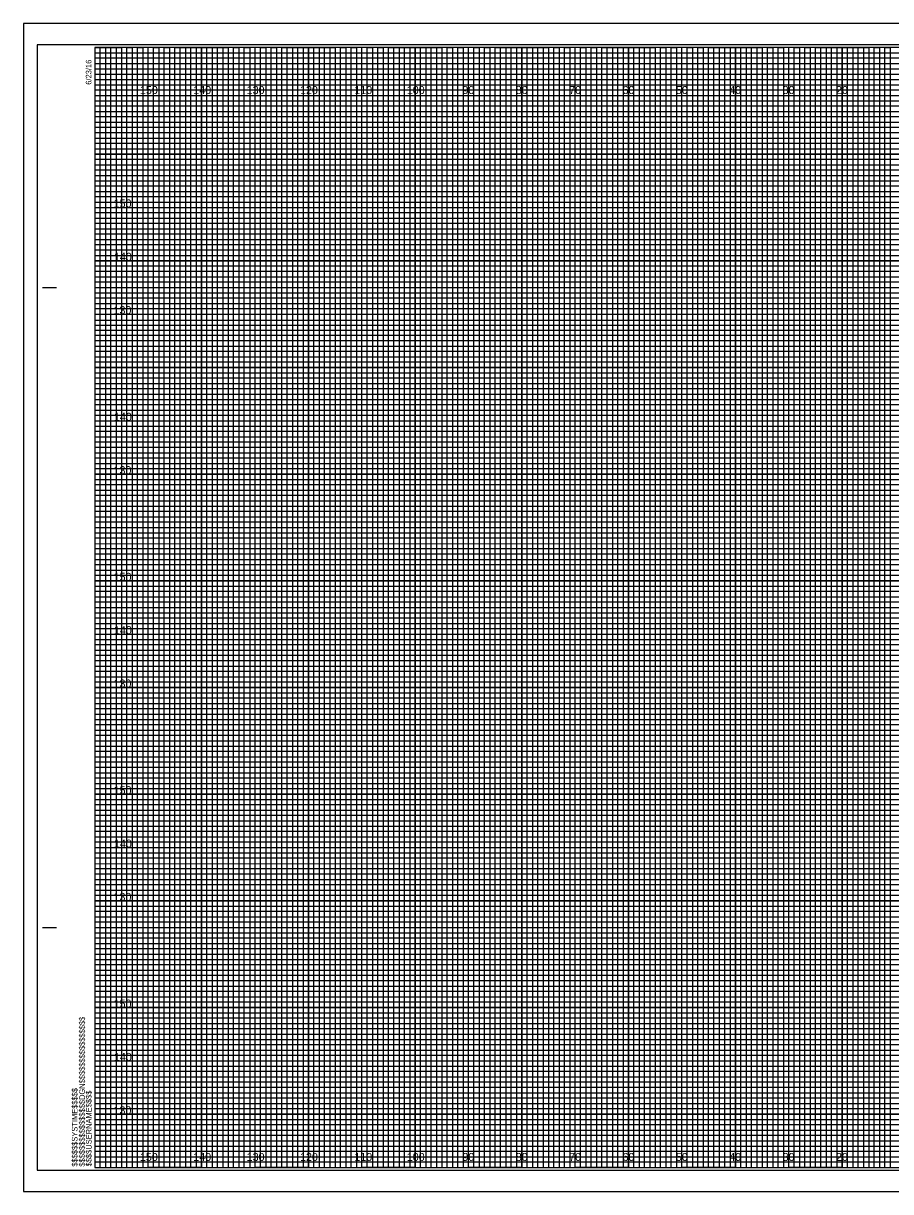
# Model space of a CAD drawing. Extents: x -13 to 323, y -5 to 2634.
# Drawn here: x -13.4 to 149.1, y 1535.5 to 1754.5 of the extents above; entities that cross this region are included whole.
import ezdxf

# ---------------------------------------------------------------- set-up
doc = ezdxf.new("R2010")
doc.units = 0
for name, color, linetype in [('Exist Cross Section Cell', 7, 'Continuous'), ('Exist XS Center Line Elevation Label', 7, 'Continuous'), ('Exist XS Ground Line', 7, 'Continuous'), ('Prop CMT Pvmt Surface Shoulder', 7, 'Continuous'), ('Prop CMT Pvmt Wedge Surface 3', 7, 'Continuous'), ('Prop CMT Shld Paved Course 1', 7, 'Continuous'), ('Prop CMT Shld Paved Course 2', 7, 'Continuous'), ('Prop CMT Shld Paved Course 3', 7, 'Continuous'), ('Prop CMT Slope Grass', 7, 'Continuous'), ('Prop CMT Subgrade Earthwork', 7, 'Continuous'), ('Scratch_Level_0', 7, 'Continuous')]:
    doc.layers.add(name, color=color, linetype=linetype)

msp = doc.modelspace()

# ---------------------------------------------------------------- linework, layer by layer
at = {"layer": 'Exist XS Center Line Elevation Label'}
for points in [[(0, 1750), (5, 1750), (5, 1540), (15, 1540), (15, 1750), (25, 1750), (25, 1540), (35, 1540), (35, 1750), (45, 1750), (45, 1540), (55, 1540), (55, 1750), (65, 1750), (65, 1540), (75, 1540), (75, 1750), (85, 1750), (85, 1540), (95, 1540), (95, 1750), (105, 1750), (105, 1540), (115, 1540), (115, 1750), (125, 1750), (125, 1540), (135, 1540), (135, 1750), (145, 1750), (145, 1540), (155, 1540)], [(0, 1745), (275, 1745)], [(0, 1725), (320, 1725), (320, 1735), (0, 1735)], [(0, 1705), (320, 1705), (320, 1715), (0, 1715)], [(0, 1685), (320, 1685), (320, 1695), (0, 1695)], [(0, 1665), (320, 1665), (320, 1675), (0, 1675)], [(0, 1645), (320, 1645), (320, 1655), (0, 1655)], [(0, 1625), (320, 1625), (320, 1635), (0, 1635)], [(0, 1605), (320, 1605), (320, 1615), (0, 1615)], [(0, 1585), (320, 1585), (320, 1595), (0, 1595)], [(0, 1565), (320, 1565), (320, 1575), (0, 1575)], [(0, 1545), (320, 1545), (320, 1555), (0, 1555)]]:
    msp.add_lwpolyline(points, dxfattribs=at)
at = {"layer": 'Exist XS Ground Line'}
for p, q in [((10, 1750), (0, 1750)), ((10, 1540), (10, 1750)), ((30, 1750), (20, 1750)), ((20, 1750), (20, 1540)), ((30, 1540), (30, 1750)), ((50, 1750), (40, 1750)), ((40, 1750), (40, 1540)), ((50, 1540), (50, 1750)), ((70, 1750), (60, 1750)), ((60, 1750), (60, 1540)), ((70, 1540), (70, 1750)), ((90, 1750), (80, 1750)), ((80, 1750), (80, 1540)), ((90, 1540), (90, 1750)), ((110, 1750), (100, 1750)), ((100, 1750), (100, 1540)), ((110, 1540), (110, 1750)), ((130, 1750), (120, 1750)), ((120, 1750), (120, 1540)), ((130, 1540), (130, 1750)), ((150, 1750), (140, 1750)), ((140, 1750), (140, 1540)), ((20, 1540), (10, 1540)), ((40, 1540), (30, 1540)), ((60, 1540), (50, 1540)), ((80, 1540), (70, 1540)), ((100, 1540), (90, 1540)), ((120, 1540), (110, 1540)), ((140, 1540), (130, 1540))]:
    msp.add_line(p, q, dxfattribs=at)
for points in [[(0, 1740), (320, 1740), (320, 1730), (0, 1730)], [(0, 1720), (320, 1720), (320, 1710), (0, 1710)], [(0, 1700), (320, 1700), (320, 1690), (0, 1690)], [(0, 1680), (320, 1680), (320, 1670), (0, 1670)], [(0, 1660), (320, 1660), (320, 1650), (0, 1650)], [(0, 1640), (320, 1640), (320, 1630), (0, 1630)], [(0, 1620), (320, 1620), (320, 1610), (0, 1610)], [(0, 1600), (320, 1600), (320, 1590), (0, 1590)], [(0, 1580), (320, 1580), (320, 1570), (0, 1570)], [(0, 1560), (320, 1560), (320, 1550), (0, 1550)]]:
    msp.add_lwpolyline(points, dxfattribs=at)
at = {"layer": 'Prop CMT Pvmt Surface Shoulder'}
for points in [[(0, 1540), (1, 1540), (1, 1750), (2, 1750), (2, 1540)], [(2, 1540), (3, 1540), (3, 1750), (4, 1750), (4, 1540)], [(5, 1540), (6, 1540), (6, 1750), (7, 1750), (7, 1540)], [(7, 1540), (8, 1540), (8, 1750), (9, 1750), (9, 1540)], [(10, 1540), (11, 1540), (11, 1750), (12, 1750), (12, 1540)], [(12, 1540), (13, 1540), (13, 1750), (14, 1750), (14, 1540)], [(15, 1540), (16, 1540), (16, 1750), (17, 1750), (17, 1540)], [(17, 1540), (18, 1540), (18, 1750), (19, 1750), (19, 1540)], [(20, 1540), (21, 1540), (21, 1750), (22, 1750), (22, 1540)], [(22, 1540), (23, 1540), (23, 1750), (24, 1750), (24, 1540)], [(25, 1540), (26, 1540), (26, 1750), (27, 1750), (27, 1540)], [(27, 1540), (28, 1540), (28, 1750), (29, 1750), (29, 1540)], [(30, 1540), (31, 1540), (31, 1750), (32, 1750), (32, 1540)], [(32, 1540), (33, 1540), (33, 1750), (34, 1750), (34, 1540)], [(35, 1540), (36, 1540), (36, 1750), (37, 1750), (37, 1540)], [(37, 1540), (38, 1540), (38, 1750), (39, 1750), (39, 1540)], [(40, 1540), (41, 1540), (41, 1750), (42, 1750), (42, 1540)], [(42, 1540), (43, 1540), (43, 1750), (44, 1750), (44, 1540)], [(45, 1540), (46, 1540), (46, 1750), (47, 1750), (47, 1540)], [(47, 1540), (48, 1540), (48, 1750), (49, 1750), (49, 1540)], [(50, 1540), (51, 1540), (51, 1750), (52, 1750), (52, 1540)], [(52, 1540), (53, 1540), (53, 1750), (54, 1750), (54, 1540)], [(55, 1540), (56, 1540), (56, 1750), (57, 1750), (57, 1540)], [(57, 1540), (58, 1540), (58, 1750), (59, 1750), (59, 1540)], [(60, 1540), (61, 1540), (61, 1750), (62, 1750), (62, 1540)], [(62, 1540), (63, 1540), (63, 1750), (64, 1750), (64, 1540)], [(65, 1540), (66, 1540), (66, 1750), (67, 1750), (67, 1540)], [(67, 1540), (68, 1540), (68, 1750), (69, 1750), (69, 1540)], [(70, 1540), (71, 1540), (71, 1750), (72, 1750), (72, 1540)], [(72, 1540), (73, 1540), (73, 1750), (74, 1750), (74, 1540)], [(75, 1540), (76, 1540), (76, 1750), (77, 1750), (77, 1540)], [(77, 1540), (78, 1540), (78, 1750), (79, 1750), (79, 1540)], [(80, 1540), (81, 1540), (81, 1750), (82, 1750), (82, 1540)], [(82, 1540), (83, 1540), (83, 1750), (84, 1750), (84, 1540)], [(85, 1540), (86, 1540), (86, 1750), (87, 1750), (87, 1540)], [(87, 1540), (88, 1540), (88, 1750), (89, 1750), (89, 1540)], [(90, 1540), (91, 1540), (91, 1750), (92, 1750), (92, 1540)], [(92, 1540), (93, 1540), (93, 1750), (94, 1750), (94, 1540)], [(95, 1540), (96, 1540), (96, 1750), (97, 1750), (97, 1540)], [(97, 1540), (98, 1540), (98, 1750), (99, 1750), (99, 1540)], [(100, 1540), (101, 1540), (101, 1750), (102, 1750), (102, 1540)], [(102, 1540), (103, 1540), (103, 1750), (104, 1750), (104, 1540)], [(105, 1540), (106, 1540), (106, 1750), (107, 1750), (107, 1540)], [(107, 1540), (108, 1540), (108, 1750), (109, 1750), (109, 1540)], [(110, 1540), (111, 1540), (111, 1750), (112, 1750), (112, 1540)], [(112, 1540), (113, 1540), (113, 1750), (114, 1750), (114, 1540)], [(115, 1540), (116, 1540), (116, 1750), (117, 1750), (117, 1540)], [(117, 1540), (118, 1540), (118, 1750), (119, 1750), (119, 1540)], [(120, 1540), (121, 1540), (121, 1750), (122, 1750), (122, 1540)], [(122, 1540), (123, 1540), (123, 1750), (124, 1750), (124, 1540)], [(125, 1540), (126, 1540), (126, 1750), (127, 1750), (127, 1540)], [(127, 1540), (128, 1540), (128, 1750), (129, 1750), (129, 1540)], [(130, 1540), (131, 1540), (131, 1750), (132, 1750), (132, 1540)], [(132, 1540), (133, 1540), (133, 1750), (134, 1750), (134, 1540)], [(135, 1540), (136, 1540), (136, 1750), (137, 1750), (137, 1540)], [(137, 1540), (138, 1540), (138, 1750), (139, 1750), (139, 1540)], [(140, 1540), (141, 1540), (141, 1750), (142, 1750), (142, 1540)], [(142, 1540), (143, 1540), (143, 1750), (144, 1750), (144, 1540)], [(145, 1540), (146, 1540), (146, 1750), (147, 1750), (147, 1540)], [(147, 1540), (148, 1540), (148, 1750), (149, 1750), (149, 1540)]]:
    msp.add_lwpolyline(points, dxfattribs=at)
at = {"layer": 'Prop CMT Pvmt Wedge Surface 3'}
for p, q in [((-9.8, 1705), (-7.3, 1705)), ((-9.7, 1705), (-7.2, 1705)), ((-9.8, 1585), (-7.3, 1585)), ((-9.7, 1585), (-7.2, 1585)), ((0, 1540), (0, 1540)), ((0, 1540), (0, 1540)), ((0, 1540), (0, 1540)), ((0, 1540), (0, 1540)), ((0, 1540), (0, 1540)), ((0, 1540), (0, 1540)), ((0, 1540), (0, 1540))]:
    msp.add_line(p, q, dxfattribs=at)
msp.add_lwpolyline([(320, 1750), (0, 1750), (0, 1540), (320, 1540)], close=True, dxfattribs=at)
at = {"layer": 'Prop CMT Shld Paved Course 1'}
for p, q in [((10, 1540), (10, 1750)), ((20, 1540), (20, 1750)), ((30, 1540), (30, 1750)), ((40, 1540), (40, 1750)), ((50, 1540), (50, 1750)), ((60, 1540), (60, 1750)), ((70, 1540), (70, 1750)), ((80, 1540), (80, 1750)), ((90, 1540), (90, 1750)), ((100, 1540), (100, 1750)), ((110, 1540), (110, 1750)), ((120, 1540), (120, 1750)), ((130, 1540), (130, 1750)), ((140, 1540), (140, 1750)), ((0, 1740), (320, 1740)), ((0, 1730), (320, 1730)), ((0, 1720), (320, 1720)), ((0, 1710), (320, 1710)), ((0, 1700), (320, 1700)), ((0, 1690), (320, 1690)), ((0, 1680), (320, 1680)), ((0, 1670), (320, 1670)), ((0, 1660), (320, 1660)), ((0, 1650), (320, 1650)), ((0, 1640), (320, 1640)), ((0, 1630), (320, 1630)), ((0, 1620), (320, 1620)), ((0, 1610), (320, 1610)), ((0, 1600), (320, 1600)), ((0, 1590), (320, 1590)), ((0, 1580), (320, 1580)), ((0, 1570), (320, 1570)), ((0, 1560), (320, 1560)), ((0, 1550), (320, 1550))]:
    msp.add_line(p, q, dxfattribs=at)
at = {"layer": 'Prop CMT Shld Paved Course 2'}
for p, q in [((323.3, 1754.5), (-13.4, 1754.5)), ((-13.4, 1754.5), (-13.4, 1535.5)), ((-13.4, 1535.5), (323.3, 1535.5))]:
    msp.add_line(p, q, dxfattribs=at)
at = {"layer": 'Prop CMT Slope Grass'}
msp.add_lwpolyline([(-10.8, 1539.5), (322.4, 1539.5), (322.4, 1750.5), (-10.8, 1750.5)], close=True, dxfattribs=at)
at = {"layer": 'Prop CMT Subgrade Earthwork'}
msp.add_lwpolyline([(-13.4, 1535.5), (323.3, 1535.5), (323.3, 1754.5), (-13.4, 1754.5)], close=True, dxfattribs=at)
at = {"layer": 'Scratch_Level_0'}
for p, q in [((0, 1749), (260, 1749)), ((260, 1747.98), (0, 1747.98)), ((0, 1747.98), (0, 1747)), ((0, 1747), (260, 1747)), ((260, 1745.89), (0, 1745.89)), ((0, 1745.89), (0, 1744)), ((0, 1744), (320, 1744))]:
    msp.add_line(p, q, dxfattribs=at)
for points in [[(0, 1743), (270, 1743), (320, 1743), (320, 1742), (0, 1742)], [(0, 1741), (320, 1741), (320, 1739), (0, 1739)], [(0, 1738), (320, 1738), (320, 1737), (0, 1736.98)], [(0, 1736), (320, 1736), (320, 1734), (0, 1734)], [(0, 1733), (320, 1733), (320, 1732), (0, 1732)], [(0, 1731), (320, 1731), (320, 1729), (0, 1729)], [(0, 1728), (320, 1728), (320, 1727), (0, 1727)], [(0, 1726), (320, 1726), (320, 1724), (0, 1724)], [(0, 1723), (320, 1723), (320, 1722), (0, 1722)], [(0, 1721), (320, 1721), (320, 1719), (0, 1719)], [(0, 1718), (320, 1718), (320, 1717), (0, 1717)], [(0, 1716), (320, 1716), (320, 1713.95), (320, 1713), (320, 1712), (0, 1712)], [(0, 1714), (320, 1714), (320, 1713), (0, 1713)], [(0, 1711), (320, 1711), (320, 1709), (0, 1709.03)], [(0, 1709.03), (320, 1709), (320, 1708), (0, 1708)], [(0, 1707), (320, 1707), (320, 1706), (0, 1706)], [(0, 1704), (320, 1704), (320, 1703), (0, 1703)], [(0, 1702), (320, 1702), (320, 1701), (0, 1701)], [(-0.07, 1698.89), (320, 1698.89), (320, 1697.88), (-0.07, 1697.88)], [(0, 1697), (320, 1697), (320, 1696), (0, 1696)], [(0, 1694), (320, 1694), (320, 1693), (0, 1693)], [(0, 1692), (320, 1692), (320, 1691), (0, 1691)], [(0, 1689), (320, 1689), (320, 1688), (0, 1688)], [(0, 1687), (320, 1687), (320, 1686), (0, 1686)], [(0, 1684), (320, 1684), (320, 1683), (0, 1683)], [(0, 1682), (320, 1682), (320, 1681), (0, 1681)], [(0, 1679), (320, 1679), (319.99, 1677.98), (0, 1678)], [(0, 1677), (320, 1677), (320, 1676), (0, 1676)], [(0, 1674), (320, 1674), (320, 1673), (0, 1673)], [(0, 1672), (320, 1672), (320, 1671), (0, 1671)], [(0, 1669), (320, 1669), (320, 1668), (0, 1668)], [(0, 1667), (320, 1667), (320, 1666), (0, 1666)], [(0, 1664), (320, 1664), (320, 1663), (0, 1663)], [(0, 1662), (320, 1662), (320, 1661), (0, 1661)], [(0, 1659), (320, 1659), (320, 1658), (0, 1658)], [(0, 1656.99), (320.07, 1656.91), (320, 1656), (0, 1656)], [(0, 1654), (320, 1654), (320, 1653), (0, 1653)], [(0, 1652), (320, 1652), (320, 1651), (0, 1651)], [(0, 1649), (320, 1649), (320, 1648), (0, 1648)], [(0, 1647), (320, 1647), (320, 1646), (0, 1646)], [(0, 1644), (320, 1644), (320, 1643), (0, 1643)], [(0, 1642), (320, 1642), (320, 1641), (0, 1641)], [(0, 1639), (320, 1639), (320, 1638), (0, 1638)], [(0, 1637), (320, 1637), (320, 1636), (0, 1636)], [(0, 1634), (320, 1634), (320, 1633), (0, 1633)], [(0, 1632), (320, 1632), (320, 1631), (0, 1631)], [(0, 1629), (320, 1629), (320, 1628), (0, 1628)], [(0, 1627), (320, 1627), (320, 1626), (0, 1626)], [(0, 1624), (320, 1624), (320, 1623), (0, 1623)], [(0, 1622), (320, 1622), (320, 1621), (0, 1621)], [(0, 1619), (320, 1619), (319.99, 1617.98), (0, 1618)], [(0, 1617), (320, 1617), (320, 1616), (0, 1616)], [(0, 1614), (320, 1614), (320, 1613), (0, 1613)], [(0, 1612), (320, 1612), (320, 1611), (0, 1611)], [(0, 1609), (320, 1609), (320, 1608), (0, 1608)], [(0, 1607), (320, 1607), (320, 1606), (0, 1606)], [(0, 1604), (320, 1604), (320, 1603), (0, 1603)], [(0, 1602), (320, 1602), (320, 1601), (0, 1601)], [(0, 1599), (320, 1599), (320, 1598), (0, 1598)], [(0, 1596.99), (320.07, 1596.91), (320, 1596), (0, 1596)], [(0, 1594), (320, 1594), (320, 1593), (0, 1593)], [(0, 1592), (320, 1592), (320, 1591), (0, 1591)], [(0, 1589), (320, 1589), (320, 1588), (0, 1588)], [(0, 1587), (320, 1587), (320, 1586), (0, 1586)], [(0, 1584), (320, 1584), (320, 1583), (0, 1583)], [(0, 1582), (320, 1582), (320, 1581), (0, 1581)], [(0, 1579), (320, 1579), (320, 1578), (0, 1578)], [(0, 1577), (320, 1577), (320, 1576), (0, 1576)], [(0, 1574), (320, 1574), (320, 1573), (0, 1573)], [(0, 1572), (320, 1572), (320, 1571), (0, 1571)], [(0, 1569), (320, 1569), (320, 1568), (0, 1568)], [(0, 1567), (320, 1567), (320, 1566), (0, 1566)], [(0, 1564), (320, 1564), (320, 1563), (0, 1563)], [(0, 1562), (320, 1562), (320, 1561), (0, 1561)], [(0, 1559), (320, 1559), (320, 1558), (0, 1558)], [(0, 1557), (320, 1557), (320, 1556), (0, 1556)], [(0, 1554), (320, 1554), (320, 1553), (0, 1553)], [(0, 1552), (320, 1552), (320, 1551), (0, 1551)], [(0, 1549), (320, 1549), (320, 1548), (0, 1548)], [(0, 1547), (320, 1547), (320, 1546), (0, 1546)], [(0, 1544), (320, 1544), (320, 1543), (0, 1543)], [(0, 1542), (320, 1542), (320, 1541), (0, 1541)]]:
    msp.add_lwpolyline(points, dxfattribs=at)

# ---------------------------------------------------------------- texts
at = {"layer": 'Exist Cross Section Cell'}
for s, p in [('150', (8.44, 1741.25)), ('140', (18.44, 1741.25)), ('130', (28.44, 1741.25)), ('120', (38.44, 1741.25)), ('110', (48.62, 1741.25)), ('100', (58.44, 1741.25)), ('90', (68.86, 1741.25)), ('80', (78.86, 1741.25)), ('70', (88.86, 1741.25)), ('60', (98.86, 1741.25)), ('50', (108.86, 1741.25)), ('40', (118.86, 1741.25)), ('30', (128.86, 1741.25)), ('20', (138.86, 1741.25)), ('150', (8.44, 1541.25)), ('140', (18.44, 1541.25)), ('130', (28.44, 1541.25)), ('120', (38.44, 1541.25)), ('110', (48.62, 1541.25)), ('100', (58.44, 1541.25)), ('90', (68.86, 1541.25)), ('80', (78.86, 1541.25)), ('70', (88.86, 1541.25)), ('60', (98.86, 1541.25)), ('50', (108.86, 1541.25)), ('40', (118.86, 1541.25)), ('30', (128.86, 1541.25)), ('20', (138.86, 1541.25))]:
    msp.add_text(s, height=1.5, dxfattribs=at).set_placement(p)
at = {"layer": 'Prop CMT Pvmt Wedge Surface 3'}
for s, p in [('6/23/16', (-0.65, 1743)), ('$$$$$$$$$$$$$$$$DGN$$$$$$$$$$$$$$$$', (-1.88, 1540.18)), ('$$$$$$SYSTIME$$$$$', (-3.26, 1540.18)), ('$$$$USERNAME$$$$', (-0.62, 1540.23))]:
    msp.add_text(s, height=1.05, rotation=90, dxfattribs=at).set_placement(p)
at = {"layer": 'Prop CMT Shld Paved Course 3'}
for s, p in [('150', (3.52, 1720)), ('140', (3.57, 1710)), ('130', (3.49, 1700)), ('140', (3.57, 1680)), ('130', (3.49, 1670)), ('150', (3.52, 1650)), ('140', (3.57, 1640)), ('130', (3.49, 1630)), ('150', (3.52, 1610)), ('140', (3.57, 1600)), ('130', (3.49, 1590)), ('150', (3.52, 1570)), ('140', (3.57, 1560)), ('130', (3.49, 1550))]:
    msp.add_text(s, height=1.5, dxfattribs=at).set_placement(p)

doc.saveas('drawing.dxf')
